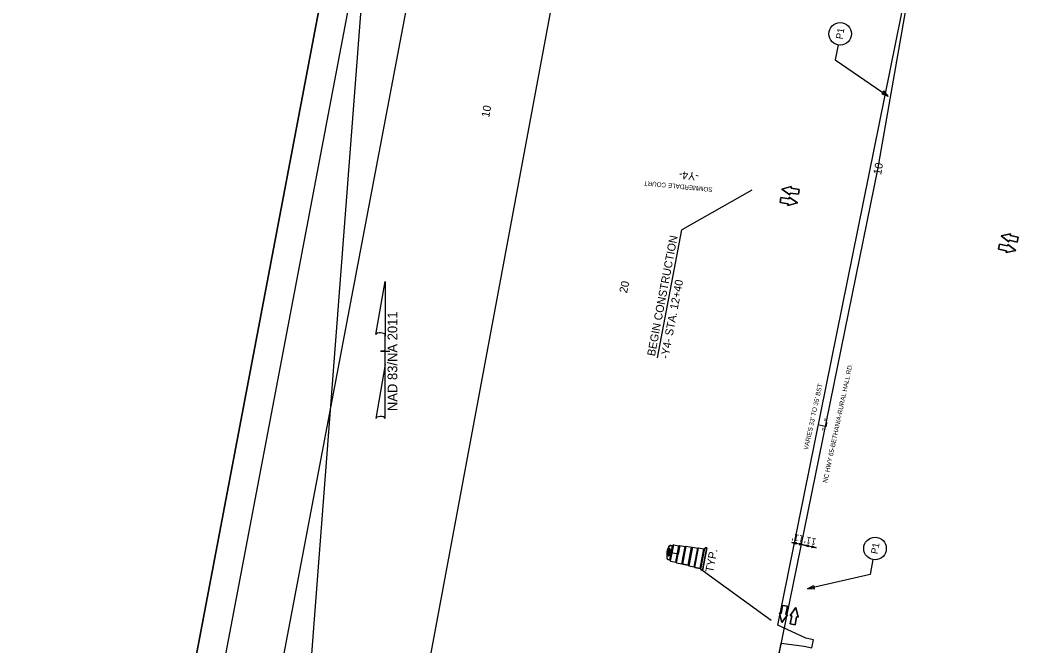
# Model space of a CAD drawing. Extents: x 1615680 to 1617075, y 898420 to 901376.
# Drawn here: x 1615680 to 1616556, y 900330 to 900877 of the extents above; entities that cross this region are included whole.
import ezdxf

# ---------------------------------------------------------------- set-up
doc = ezdxf.new("R2010")
doc.units = 0
for name, color, linetype in [('Default', 7, 'Continuous'), ('DEV BORDER CELL', 7, 'Continuous'), ('DEV DIRECTION OF TRAFFIC FLOW ARROW CELL', 7, 'Continuous'), ('DEV DRUM SECTIONAL VIEW CELL', 7, 'Continuous'), ('Old_Level_11', 7, 'Continuous'), ('Prop DSN Text', 7, 'Continuous'), ('Prop Horizontal Alignment Tick Label', 7, 'Continuous'), ('Prop North Arrow NAD83 for Plan Sheets CELL', 7, 'Continuous'), ('Scratch_Level_0', 7, 'Continuous'), ('Sheet Clip Boundary CELL', 7, 'Continuous'), ('Sheet Plot Border Outside CELL', 7, 'Continuous')]:
    doc.layers.add(name, color=color, linetype=linetype)

msp = doc.modelspace()

# ---------------------------------------------------------------- linework, layer by layer
at = {"layer": 'Default'}
for points in [[(1616395.16, 900855.34), (1616392.7, 900842.4), (1616439.1, 900810.63)], [(1616425.7, 900405.07), (1616423.24, 900392.13), (1616368.43, 900379.57)]]:
    msp.add_lwpolyline(points, dxfattribs=at)
for points in [[(1616433.44, 900812.62), (1616439.1, 900810.63), (1616435.19, 900815.18)], [(1616358.52, 900418.67), (1616354.7, 900420.21), (1616358.84, 900420.05), (1616358.18, 900419.46)], [(1616361.64, 900419.42), (1616365.46, 900417.88), (1616361.32, 900418.04), (1616361.98, 900418.63)], [(1616369.27, 900416.34), (1616365.46, 900417.88), (1616369.59, 900417.73), (1616368.93, 900417.13)], [(1616372.4, 900417.1), (1616376.21, 900415.56), (1616372.07, 900415.71), (1616372.73, 900416.31)], [(1616374.43, 900379.35), (1616368.43, 900379.57), (1616373.73, 900382.38)]]:
    msp.add_lwpolyline(points, close=True, dxfattribs=at)
for centre in [(1616397, 900865.06), (1616427.54, 900414.79)]:
    msp.add_circle(centre, 9.89, dxfattribs=at)
at = {"layer": 'DEV BORDER CELL'}
msp.add_lwpolyline([(1616014.55, 901139.21), (1615734.74, 899665.53), (1616766.32, 899469.67), (1617046.12, 900943.35)], close=True, dxfattribs=at)
at = {"layer": 'DEV DIRECTION OF TRAFFIC FLOW ARROW CELL'}
for p, q in [((1616354.32, 900731.54), (1616346.09, 900729.18)), ((1616346.09, 900729.18), (1616354.32, 900731.54)), ((1616346.09, 900729.18), (1616353.16, 900724.33)), ((1616353.16, 900724.33), (1616346.09, 900729.18)), ((1616354.09, 900730.08), (1616354.32, 900731.54)), ((1616354.32, 900731.54), (1616354.09, 900730.08)), ((1616361.19, 900728.93), (1616354.09, 900730.08)), ((1616354.09, 900730.08), (1616361.19, 900728.93)), ((1616360.5, 900724.64), (1616361.19, 900728.93)), ((1616361.19, 900728.93), (1616360.5, 900724.64)), ((1616345.24, 900721.84), (1616344.54, 900717.55)), ((1616344.54, 900717.55), (1616345.24, 900721.84)), ((1616344.54, 900717.55), (1616351.65, 900716.4)), ((1616351.65, 900716.4), (1616344.54, 900717.55)), ((1616352.34, 900720.69), (1616345.24, 900721.84)), ((1616345.24, 900721.84), (1616352.34, 900720.69)), ((1616351.41, 900714.94), (1616359.65, 900717.3)), ((1616359.65, 900717.3), (1616351.41, 900714.94)), ((1616352.58, 900722.15), (1616352.34, 900720.69)), ((1616352.34, 900720.69), (1616352.58, 900722.15)), ((1616359.65, 900717.3), (1616352.58, 900722.15)), ((1616352.58, 900722.15), (1616359.65, 900717.3)), ((1616353.16, 900724.33), (1616353.39, 900725.79)), ((1616353.39, 900725.79), (1616353.16, 900724.33)), ((1616353.39, 900725.79), (1616360.5, 900724.64)), ((1616360.5, 900724.64), (1616353.39, 900725.79)), ((1616351.65, 900716.4), (1616351.41, 900714.94)), ((1616351.41, 900714.94), (1616351.65, 900716.4)), ((1616546.08, 900690.16), (1616537.72, 900688.27)), ((1616537.72, 900688.27), (1616546.08, 900690.16)), ((1616537.72, 900688.27), (1616544.5, 900683.03)), ((1616544.5, 900683.03), (1616537.72, 900688.27)), ((1616544.5, 900683.03), (1616544.82, 900684.47)), ((1616544.82, 900684.47), (1616544.5, 900683.03)), ((1616544.82, 900684.47), (1616551.85, 900682.91)), ((1616551.85, 900682.91), (1616544.82, 900684.47)), ((1616545.76, 900688.72), (1616546.08, 900690.16)), ((1616546.08, 900690.16), (1616545.76, 900688.72)), ((1616552.79, 900687.16), (1616545.76, 900688.72)), ((1616545.76, 900688.72), (1616552.79, 900687.16)), ((1616551.85, 900682.91), (1616552.79, 900687.16)), ((1616552.79, 900687.16), (1616551.85, 900682.91)), ((1616536.45, 900681), (1616535.51, 900676.75)), ((1616535.51, 900676.75), (1616536.45, 900681)), ((1616535.51, 900676.75), (1616542.54, 900675.19)), ((1616542.54, 900675.19), (1616535.51, 900676.75)), ((1616543.48, 900679.44), (1616536.45, 900681)), ((1616536.45, 900681), (1616543.48, 900679.44)), ((1616542.22, 900673.75), (1616550.58, 900675.64)), ((1616550.58, 900675.64), (1616542.22, 900673.75)), ((1616542.54, 900675.19), (1616542.22, 900673.75)), ((1616542.22, 900673.75), (1616542.54, 900675.19)), ((1616543.8, 900680.88), (1616543.48, 900679.44)), ((1616543.48, 900679.44), (1616543.8, 900680.88)), ((1616550.58, 900675.64), (1616543.8, 900680.88)), ((1616543.8, 900680.88), (1616550.58, 900675.64)), ((1616345.37, 900358.02), (1616343.92, 900358.29)), ((1616343.92, 900358.29), (1616346.06, 900349.99)), ((1616346.06, 900349.99), (1616343.92, 900358.29)), ((1616343.92, 900358.29), (1616345.37, 900358.02)), ((1616346.72, 900365.09), (1616345.37, 900358.02)), ((1616345.37, 900358.02), (1616346.72, 900365.09)), ((1616350.99, 900364.28), (1616346.72, 900365.09)), ((1616346.72, 900365.09), (1616350.99, 900364.28)), ((1616349.64, 900357.2), (1616350.99, 900364.28)), ((1616350.99, 900364.28), (1616349.64, 900357.2)), ((1616358.3, 900363.22), (1616353.27, 900356.29)), ((1616353.27, 900356.29), (1616358.3, 900363.22)), ((1616360.44, 900354.92), (1616358.3, 900363.22)), ((1616358.3, 900363.22), (1616360.44, 900354.92)), ((1616346.06, 900349.99), (1616351.1, 900356.93)), ((1616351.1, 900356.93), (1616346.06, 900349.99)), ((1616351.1, 900356.93), (1616349.64, 900357.2)), ((1616349.64, 900357.2), (1616351.1, 900356.93)), ((1616353.27, 900356.29), (1616354.72, 900356.01)), ((1616354.72, 900356.01), (1616353.27, 900356.29)), ((1616354.72, 900356.01), (1616353.37, 900348.94)), ((1616353.37, 900348.94), (1616354.72, 900356.01)), ((1616357.64, 900348.13), (1616358.99, 900355.2)), ((1616358.99, 900355.2), (1616357.64, 900348.13)), ((1616358.99, 900355.2), (1616360.44, 900354.92)), ((1616360.44, 900354.92), (1616358.99, 900355.2)), ((1616353.37, 900348.94), (1616357.64, 900348.13)), ((1616357.64, 900348.13), (1616353.37, 900348.94))]:
    msp.add_line(p, q, dxfattribs=at)
at = {"layer": 'DEV DRUM SECTIONAL VIEW CELL'}
for p, q in [((1616248, 900414.54), (1616247.93, 900414.55)), ((1616248.14, 900404.94), (1616250.48, 900417.26)), ((1616248.71, 900403.75), (1616251.45, 900418.16)), ((1616250.48, 900417.26), (1616249.04, 900417.53)), ((1616251.45, 900418.16), (1616256.07, 900417.28)), ((1616253.33, 900402.88), (1616256.07, 900417.28)), ((1616254.04, 900402.38), (1616256.9, 900417.48)), ((1616256.07, 900417.28), (1616256.9, 900417.48)), ((1616256.9, 900417.48), (1616261.52, 900416.6)), ((1616258.65, 900401.51), (1616261.52, 900416.6)), ((1616259.36, 900401.01), (1616262.36, 900416.81)), ((1616261.52, 900416.6), (1616262.36, 900416.81)), ((1616262.36, 900416.81), (1616266.97, 900415.93)), ((1616263.98, 900400.13), (1616266.97, 900415.93)), ((1616264.68, 900399.64), (1616267.81, 900416.13)), ((1616266.97, 900415.93), (1616267.81, 900416.13)), ((1616267.81, 900416.13), (1616272.43, 900415.26)), ((1616269.3, 900398.76), (1616272.43, 900415.26)), ((1616270, 900398.27), (1616273.26, 900415.46)), ((1616272.43, 900415.26), (1616273.26, 900415.46)), ((1616273.26, 900415.46), (1616277.88, 900414.58)), ((1616274.62, 900397.39), (1616277.88, 900414.58)), ((1616275.3, 900396.79), (1616278.74, 900414.89)), ((1616276.7, 900395.73), (1616280.42, 900415.36)), ((1616277.88, 900414.58), (1616278.72, 900414.78)), ((1616280.42, 900415.36), (1616279.65, 900415.51)), ((1616248.14, 900404.94), (1616246.7, 900405.22)), ((1616246.83, 900408.38), (1616246.76, 900408.39)), ((1616248.71, 900403.75), (1616253.33, 900402.88)), ((1616253.33, 900402.88), (1616254.04, 900402.38)), ((1616254.04, 900402.38), (1616258.65, 900401.51)), ((1616258.65, 900401.51), (1616259.36, 900401.01)), ((1616259.36, 900401.01), (1616263.98, 900400.13)), ((1616263.98, 900400.13), (1616264.68, 900399.64)), ((1616264.68, 900399.64), (1616269.3, 900398.76)), ((1616269.3, 900398.76), (1616270, 900398.27)), ((1616270, 900398.27), (1616274.62, 900397.39)), ((1616274.62, 900397.39), (1616275.32, 900396.9)), ((1616276.7, 900395.73), (1616275.93, 900395.88))]:
    msp.add_line(p, q, dxfattribs=at)
for points in [[(1616254.04, 900402.38), (1616255.47, 900409.93), (1616247.77, 900411.39), (1616247.7, 900411.02), (1616247.66, 900410.73), (1616247.62, 900410.44), (1616247.58, 900410.13), (1616247.54, 900409.79), (1616247.51, 900409.44), (1616247.49, 900409.06), (1616247.47, 900408.8), (1616247.43, 900408.67), (1616247.35, 900408.56), (1616247.24, 900408.47), (1616247.13, 900408.41), (1616247.02, 900408.38), (1616246.91, 900408.37), (1616246.7, 900408.41), (1616246.59, 900408.46), (1616246.47, 900408.56), (1616246.39, 900408.67), (1616246.33, 900408.83), (1616246.32, 900408.95), (1616246.34, 900409.24), (1616246.36, 900409.62), (1616246.43, 900410.41), (1616246.51, 900410.97), (1616246.58, 900411.39), (1616246.62, 900411.61), (1616245.65, 900411.8), (1616245.57, 900411.4), (1616245.49, 900410.87), (1616245.43, 900410.34), (1616245.38, 900409.77), (1616245.35, 900409.22), (1616245.33, 900408.63), (1616245.34, 900407.94), (1616245.36, 900407.53), (1616245.41, 900406.87), (1616245.44, 900406.59), (1616245.47, 900406.4), (1616245.53, 900406.2), (1616245.62, 900406), (1616245.77, 900405.78), (1616245.93, 900405.61), (1616246.08, 900405.48), (1616246.26, 900405.37), (1616246.45, 900405.28), (1616246.7, 900405.22), (1616248.14, 900404.94), (1616248.17, 900404.79), (1616248.22, 900404.64), (1616248.31, 900404.43), (1616248.41, 900404.22), (1616248.51, 900404.03), (1616248.71, 900403.75), (1616253.33, 900402.88)], [(1616256.9, 900417.48), (1616255.47, 900409.93), (1616247.77, 900411.39), (1616247.9, 900412.04), (1616248.02, 900412.48), (1616248.11, 900412.86), (1616248.22, 900413.18), (1616248.32, 900413.54), (1616248.42, 900413.82), (1616248.45, 900413.96), (1616248.45, 900414.09), (1616248.39, 900414.25), (1616248.3, 900414.37), (1616248.19, 900414.47), (1616248.08, 900414.53), (1616247.93, 900414.55), (1616247.75, 900414.56), (1616247.59, 900414.5), (1616247.49, 900414.44), (1616247.41, 900414.36), (1616247.35, 900414.29), (1616247.31, 900414.2), (1616247.23, 900413.95), (1616247.15, 900413.69), (1616247.07, 900413.43), (1616246.98, 900413.17), (1616246.9, 900412.83), (1616246.8, 900412.46), (1616246.73, 900412.17), (1616246.68, 900411.92), (1616246.62, 900411.61), (1616245.65, 900411.8), (1616245.74, 900412.25), (1616245.82, 900412.6), (1616245.94, 900413.08), (1616246.03, 900413.41), (1616246.14, 900413.78), (1616246.28, 900414.2), (1616246.45, 900414.67), (1616246.63, 900415.14), (1616246.86, 900415.69), (1616247.08, 900416.15), (1616247.27, 900416.54), (1616247.36, 900416.72), (1616247.46, 900416.89), (1616247.59, 900417.04), (1616247.74, 900417.2), (1616247.89, 900417.3), (1616248.07, 900417.41), (1616248.25, 900417.48), (1616248.45, 900417.53), (1616248.62, 900417.56), (1616248.82, 900417.56), (1616248.97, 900417.54), (1616249.04, 900417.53), (1616250.48, 900417.26), (1616250.67, 900417.52), (1616250.78, 900417.65), (1616250.92, 900417.77), (1616251.07, 900417.91), (1616251.26, 900418.05), (1616251.37, 900418.11), (1616251.45, 900418.16), (1616256.07, 900417.28)], [(1616258.65, 900401.51), (1616261.52, 900416.6), (1616262.36, 900416.81), (1616266.97, 900415.93), (1616267.81, 900416.13), (1616264.68, 900399.64), (1616263.98, 900400.13), (1616259.36, 900401.01)], [(1616269.3, 900398.76), (1616272.43, 900415.26), (1616273.26, 900415.46), (1616277.88, 900414.58), (1616278.72, 900414.78), (1616278.76, 900414.98), (1616278.81, 900415.09), (1616278.89, 900415.22), (1616279, 900415.34), (1616279.09, 900415.41), (1616279.22, 900415.47), (1616279.37, 900415.51), (1616279.48, 900415.52), (1616279.58, 900415.52), (1616279.65, 900415.51), (1616280.42, 900415.36), (1616276.7, 900395.73), (1616275.93, 900395.88), (1616275.82, 900395.91), (1616275.7, 900395.96), (1616275.6, 900396.03), (1616275.51, 900396.1), (1616275.45, 900396.18), (1616275.37, 900396.3), (1616275.32, 900396.44), (1616275.29, 900396.58), (1616275.29, 900396.67), (1616275.3, 900396.79), (1616275.32, 900396.9), (1616274.62, 900397.39), (1616270, 900398.27)]]:
    msp.add_lwpolyline(points, close=True, dxfattribs=at)
for centre, radius, start, end in [((1616263.03, 900408.5), 17.69, 152.30015, 186.19859), ((1616264, 900408.31), 17.69, 160.57536, 177.92338), ((1616247.83, 900414.01), 0.548, 79.24937, 160.57536), ((1616248.75, 900415.99), 1.57, 79.24937, 152.30015), ((1616265.15, 900408.09), 17.69, 161.10062, 177.39812), ((1616247.9, 900414), 0.548, 341.10062, 79.24937), ((1616252.75, 900415.78), 2.71, 118.73583, 146.94336), ((1616279.51, 900414.74), 0.783, 79.24937, 169.24937), ((1616247, 900406.76), 1.57, 186.19859, 259.24937), ((1616246.87, 900408.93), 0.548, 177.92338, 259.24937), ((1616246.93, 900408.92), 0.548, 259.24937, 357.39812), ((1616250.8, 900405.49), 2.71, 191.55539, 219.76292), ((1616276.07, 900396.65), 0.783, 169.24937, 259.24937)]:
    msp.add_arc(centre, radius, start, end, dxfattribs=at)
at = {"layer": 'Old_Level_11'}
msp.add_line((1616376.21, 900415.56), (1616354.7, 900420.21), dxfattribs=at)
at = {"layer": 'Prop DSN Text'}
for p, q in [((1616319.78, 900728.21), (1616258.5, 900693.45)), ((1616237.24, 900581.47), (1616258.5, 900693.45)), ((1616336.66, 900352), (1616275.93, 900395.88))]:
    msp.add_line(p, q, dxfattribs=at)
at = {"layer": 'Prop North Arrow NAD83 for Plan Sheets CELL'}
for p, q in [((1615990.96, 900601.99), (1615999.16, 900648.34)), ((1615999.21, 900648.34), (1615999.16, 900648.34)), ((1615999.21, 900648.34), (1615999.16, 900648.34)), ((1615999.21, 900648.34), (1615999.21, 900600.54)), ((1615999.21, 900575.74), (1615999.21, 900601.94)), ((1615999.21, 900600.54), (1615999.21, 900601.89)), ((1615995.21, 900587.34), (1615995.16, 900587.34)), ((1615998.76, 900587.34), (1615995.21, 900587.34)), ((1615995.26, 900587.34), (1616003.26, 900587.34)), ((1615999.21, 900575.74), (1615990.86, 900528.49)), ((1615999.26, 900528.69), (1615999.21, 900575.74))]:
    msp.add_line(p, q, dxfattribs=at)
for centre, start_param, end_param in [((1615995.1, 900601.49), 0.216388, 2.908219), ((1615995.1, 900528.32), 0.201328, 3.141593)]:
    msp.add_ellipse(centre, major_axis=(4.23, -0.03), ratio=0.461098, start_param=start_param, end_param=end_param, dxfattribs=at)
at = {"layer": 'Scratch_Level_0'}
for points in [[(1616054.34, 901080.76), (1615793.19, 899705.33), (1616726.52, 899528.12), (1616890.46, 900391.55), (1616774.26, 900413.61), (1616871.48, 900925.61)], [(1616209.3, 899662.81), (1616429.94, 900746.4), (1616473.81, 900995.89), (1616176.29, 901060.7), (1615925.06, 899711.77)], [(1616209.3, 899662.81), (1616345.54, 900332.12), (1616365.47, 900329.48), (1616372.31, 900327.99), (1616373.8, 900334.83), (1616366.96, 900336.32), (1616342.58, 900347.76), (1616473.81, 900995.89), (1616176.29, 901060.7), (1615925.06, 899711.77)]]:
    msp.add_lwpolyline(points, close=True, dxfattribs=at)
at = {"layer": 'Sheet Clip Boundary CELL'}
msp.add_lwpolyline([(1616176.29, 901060.7), (1616913.78, 900900.04), (1616896.28, 900812.91), (1616872.94, 900688.21), (1616835.87, 900695.21), (1616753.94, 900262.18), (1616898.09, 900233.43), (1616663.91, 899565.73), (1616252.62, 899604.04), (1615894.68, 899796.73), (1615981.58, 900932.46), (1616145.94, 900899.57)], close=True, dxfattribs=at)
at = {"layer": 'Sheet Plot Border Outside CELL'}
for points in [[(1616760.47, 899304.87), (1615679.78, 899510.06), (1615994.65, 901168.43), (1617075.34, 900963.24)], [(1616760.47, 899304.87), (1617075.34, 900963.24), (1615994.65, 901168.43), (1615679.78, 899510.06)]]:
    msp.add_lwpolyline(points, close=True, dxfattribs=at)

# ---------------------------------------------------------------- texts
at = {"layer": 'Default'}
for s, height, rotation, p in [('P1', 6, 79.24933, (1616399, 900859.92)), ('SOMMERDALE COURT', 4, 174.35899, (1616285.65, 900730.54)), ('NC HWY 65-BETHANIA-RURAL HALL RD.', 4, 77.8978, (1616385.64, 900471.99)), ("VARIES 33' TO 35' BST", 4, 77.5816, (1616368.9, 900500.71)), ("11'", 6, 167.78215, (1616365.94, 900425.67)), ("11'", 6, 167.78215, (1616376.69, 900423.35)), ('TYP.', 7, 79.2494, (1616285.91, 900393.43)), ('P1', 6, 79.2494, (1616429.7, 900409.62))]:
    msp.add_text(s, height=height, rotation=rotation, dxfattribs=at).set_placement(p)
at = {"layer": 'Prop DSN Text'}
for s, p in [('BEGIN CONSTRUCTION', (1616234.99, 900582.7)), ('-Y4- STA. 12+40', (1616246.78, 900580.47))]:
    msp.add_text(s, height=7, rotation=79.24933, dxfattribs=at).set_placement(p)
at = {"layer": 'Prop Horizontal Alignment Tick Label'}
for s, rotation, p in [('10', 79.16004, (1616090.03, 900791.5)), ('-Y4-', 174.49383, (1616273.75, 900743.48)), ('10', 79.16004, (1616432.78, 900741.27)), ('20', 77.70978, (1616210.56, 900637.8)), ('-L-', 76.96721, (1616384.18, 900517.18))]:
    msp.add_text(s, height=7, rotation=rotation, dxfattribs=at).set_placement(p)
at = {"layer": 'Prop North Arrow NAD83 for Plan Sheets CELL'}
msp.add_text('NAD 83/NA 2011', height=8.5, rotation=90, dxfattribs=at).set_placement((1616009.73, 900535.03))

doc.saveas('drawing.dxf')
